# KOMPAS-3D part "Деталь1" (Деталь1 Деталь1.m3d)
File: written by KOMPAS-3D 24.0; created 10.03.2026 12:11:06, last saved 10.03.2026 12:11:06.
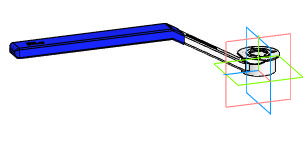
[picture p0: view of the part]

Document properties: Автор: R2D2; Полное имя файла: E:\Работа\Зайцев\BV3232P(4pc)-FP-3WL-F-ISO-H Кран шаровой DN.ru Ду15-100 Ру16\DN25\исходные материалы\Деталь1 Деталь1.m3d

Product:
- Body: Твердое тело1  | qty 1
- Part/product: Деталь1
    additional columns: Типовые

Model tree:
1. Твердое тело1  (labels: Твердое тело1)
